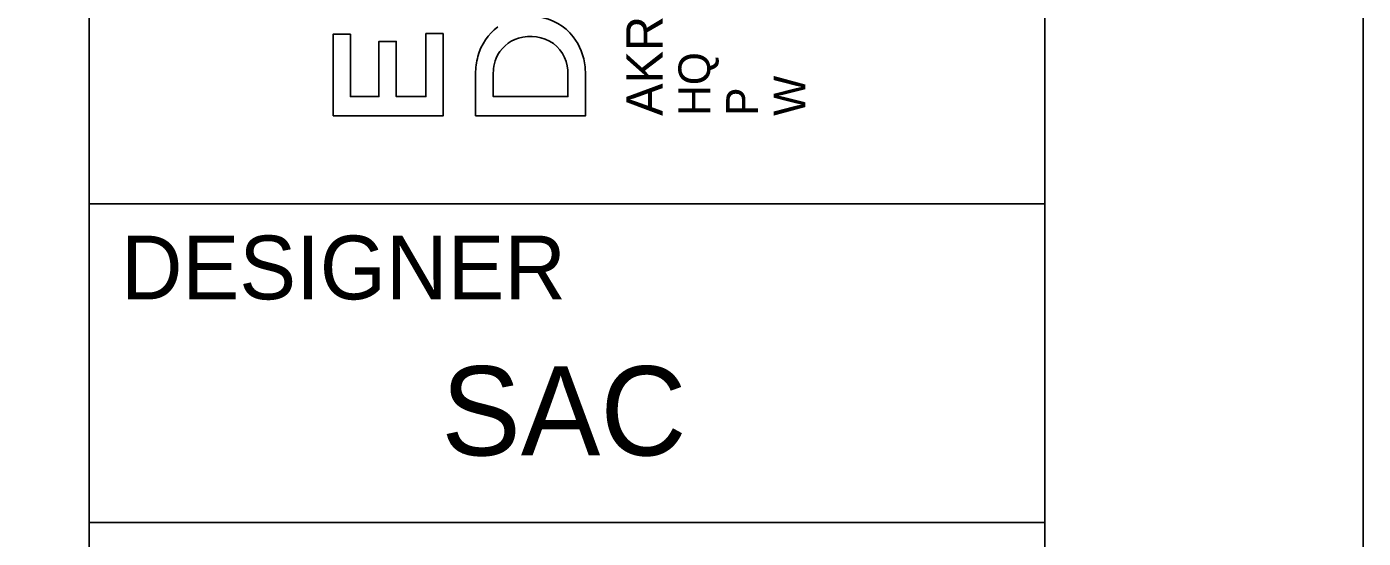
# Model space of a CAD drawing. Extents: x 0 to 34, y -1.2 to 22.
# Drawn here: x 31.902 to 34, y 2.475 to 3.278 of the extents above; entities that cross this region are included whole.
import ezdxf

# ---------------------------------------------------------------- set-up
doc = ezdxf.new("R2010")
doc.units = 0
for name, color, linetype in [('SH_Border', 7, 'Continuous'), ('SH_Cut_Line', 7, 'Continuous'), ('SH_Data', 7, 'Continuous')]:
    doc.layers.add(name, color=color, linetype=linetype)

msp = doc.modelspace()

# ---------------------------------------------------------------- linework, layer by layer
at = {"layer": 'SH_Border'}
for p, q in [((32, 0.5), (32, 21.5)), ((32, 3), (33.5, 3)), ((32, 2.5), (33.5, 2.5))]:
    msp.add_line(p, q, dxfattribs=at)
msp.add_lwpolyline([(1.5, 21.5), (33.5, 21.5), (33.5, 0.5), (1.5, 0.5)], close=True, dxfattribs=at)
at = {"layer": 'SH_Cut_Line'}
msp.add_lwpolyline([(0, 0), (34, 0), (34, 22), (0, 22)], close=True, dxfattribs=at)
at = {"layer": 'SH_Data'}
for p, q in [((32.383, 3.1379), (32.383, 3.266)), ((32.383, 3.266), (32.4101, 3.266)), ((32.4101, 3.266), (32.4101, 3.1683)), ((32.455, 3.1683), (32.455, 3.2549)), ((32.455, 3.2549), (32.4822, 3.2549)), ((32.4822, 3.2549), (32.4822, 3.1683)), ((32.5286, 3.1683), (32.5286, 3.2672)), ((32.5286, 3.2672), (32.5557, 3.2672)), ((32.5557, 3.2672), (32.5557, 3.1379)), ((32.6347, 3.2118), (32.6341, 3.2023)), ((32.7785, 3.215), (32.7792, 3.2021)), ((32.6064, 3.138), (32.6064, 3.204)), ((32.6341, 3.2023), (32.6341, 3.1684)), ((32.7515, 3.1683), (32.7515, 3.2024)), ((32.7792, 3.2021), (32.7792, 3.138)), ((32.4101, 3.1683), (32.455, 3.1683)), ((32.4822, 3.1683), (32.5286, 3.1683)), ((32.6341, 3.1684), (32.7515, 3.1683)), ((32.5557, 3.1379), (32.383, 3.1379)), ((32.7792, 3.138), (32.6064, 3.138))]:
    msp.add_line(p, q, dxfattribs=at)
msp.add_lwpolyline([(32.383, 3.1379), (32.383, 3.266), (32.4101, 3.266), (32.4101, 3.1683), (32.455, 3.1683), (32.455, 3.2549), (32.4822, 3.2549), (32.4822, 3.1683), (32.5286, 3.1683), (32.5286, 3.2672), (32.5557, 3.2672), (32.5557, 3.1379)], close=True, dxfattribs=at)
for points in [[(32.7785, 3.215), (32.7792, 3.2021), (32.7792, 3.138), (32.6064, 3.138)], [(32.6347, 3.2118), (32.6341, 3.2023), (32.6341, 3.1684), (32.7515, 3.1683), (32.7515, 3.2024)], [(32.6064, 3.138), (32.6064, 3.204)]]:
    msp.add_lwpolyline(points, dxfattribs=at)
for centre, radius, start, end in [((32.6939, 3.2089), 0.0865, 127.2362, 165.148), ((32.6939, 3.2089), 0.0865, 127.2362, 165.148), ((32.6946, 3.2113), 0.0827, 37.8521, 82.402), ((32.6946, 3.2113), 0.0827, 37.8521, 82.402), ((32.6889, 3.2078), 0.054, 106.1881, 157.3861), ((32.6889, 3.2078), 0.054, 106.1881, 157.3861), ((32.6928, 3.1986), 0.0639, 55.6727, 107.2093), ((32.6928, 3.1986), 0.0639, 55.6727, 107.2093), ((32.6859, 3.2057), 0.0931, 5.7333, 37.304), ((32.6859, 3.2057), 0.0931, 5.7333, 37.304), ((32.7143, 3.2028), 0.1078, 164.7861, 179.3704), ((32.7143, 3.2028), 0.1078, 164.7861, 179.3704), ((32.6929, 3.205), 0.0587, 357.4662, 52.2665), ((32.6929, 3.205), 0.0587, 357.4662, 52.2665), ((32.6983, 3.2039), 0.0641, 157.3571, 172.9275), ((32.6983, 3.2039), 0.0641, 157.3571, 172.9275)]:
    msp.add_arc(centre, radius, start, end, dxfattribs=at)

# ---------------------------------------------------------------- texts
for s, height, p in [('AKRON / CLEVELAND / COLUMBUS', 0.056969, (32.9001, 3.138)), ('HQ ', 0.04985, (32.9749, 3.138)), ('W', 0.0498, (33.1244, 3.138)), ('P', 0.0498, (33.0497, 3.138))]:
    msp.add_text(s, height=height, rotation=90, dxfattribs=at).set_placement(p)
for s, height, p in [('DESIGNER', 0.1, (32.05, 2.85)), ('SAC', 0.14, (32.5528, 2.605))]:
    msp.add_text(s, height=height, dxfattribs=at).set_placement(p)

doc.saveas('drawing.dxf')
